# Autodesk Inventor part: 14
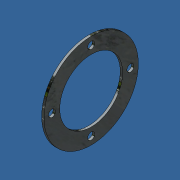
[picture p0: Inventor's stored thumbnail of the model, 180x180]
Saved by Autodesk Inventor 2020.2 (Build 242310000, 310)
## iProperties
Created: 2016-09
Part Number: 14
Material: Steel
Document SubType Name: Modeling
Designer: Mike Taylor
Mass: 141.976 g
Surface Area: 142.817 cm^2
Volume: 18.0861 cm^3
Density: 7.85 g/cm^3
Appearance: Zinc
Translation Standard: STEP AP214IS
FileName: 29_5060_0_1.stp
PreProcessor: ACIS
PostProcessor: Build: 160, Release: 2012 RTM - Date: Tue 03/01/2011
Sent Units: centimeter
Uncertainty: 0.0
Author: Mike Taylor
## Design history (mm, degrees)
node "141"
sketch "Sketch1"
  geometry: C1 r 60 at (0, 0) reference; C2 r 40 at (0, 0) reference; A1 r 50 centre (0, 0) between (0, -50) and (-50, 0); 3 further points
  constraints: 4 point on circle, 2 horizontal alignment, 2 vertical alignment, 1 centre point, 1 coincident
  dimensions: "d0" = 100 diameter of A1
hole "Hole1" sketch "Sketch1" at (0, -50), (-50, 0), (0, 50), (50, 0) diameter "d1" = 9; stored, may be unused: countersink angle "d5" = 90 deg, drill point angle "d7" = 118 deg; dims "d2" = 16.002, "d3" = 4, "d4" = 2, "d6" = 8
node "14"
node "Base1"
